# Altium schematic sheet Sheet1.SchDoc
size A4
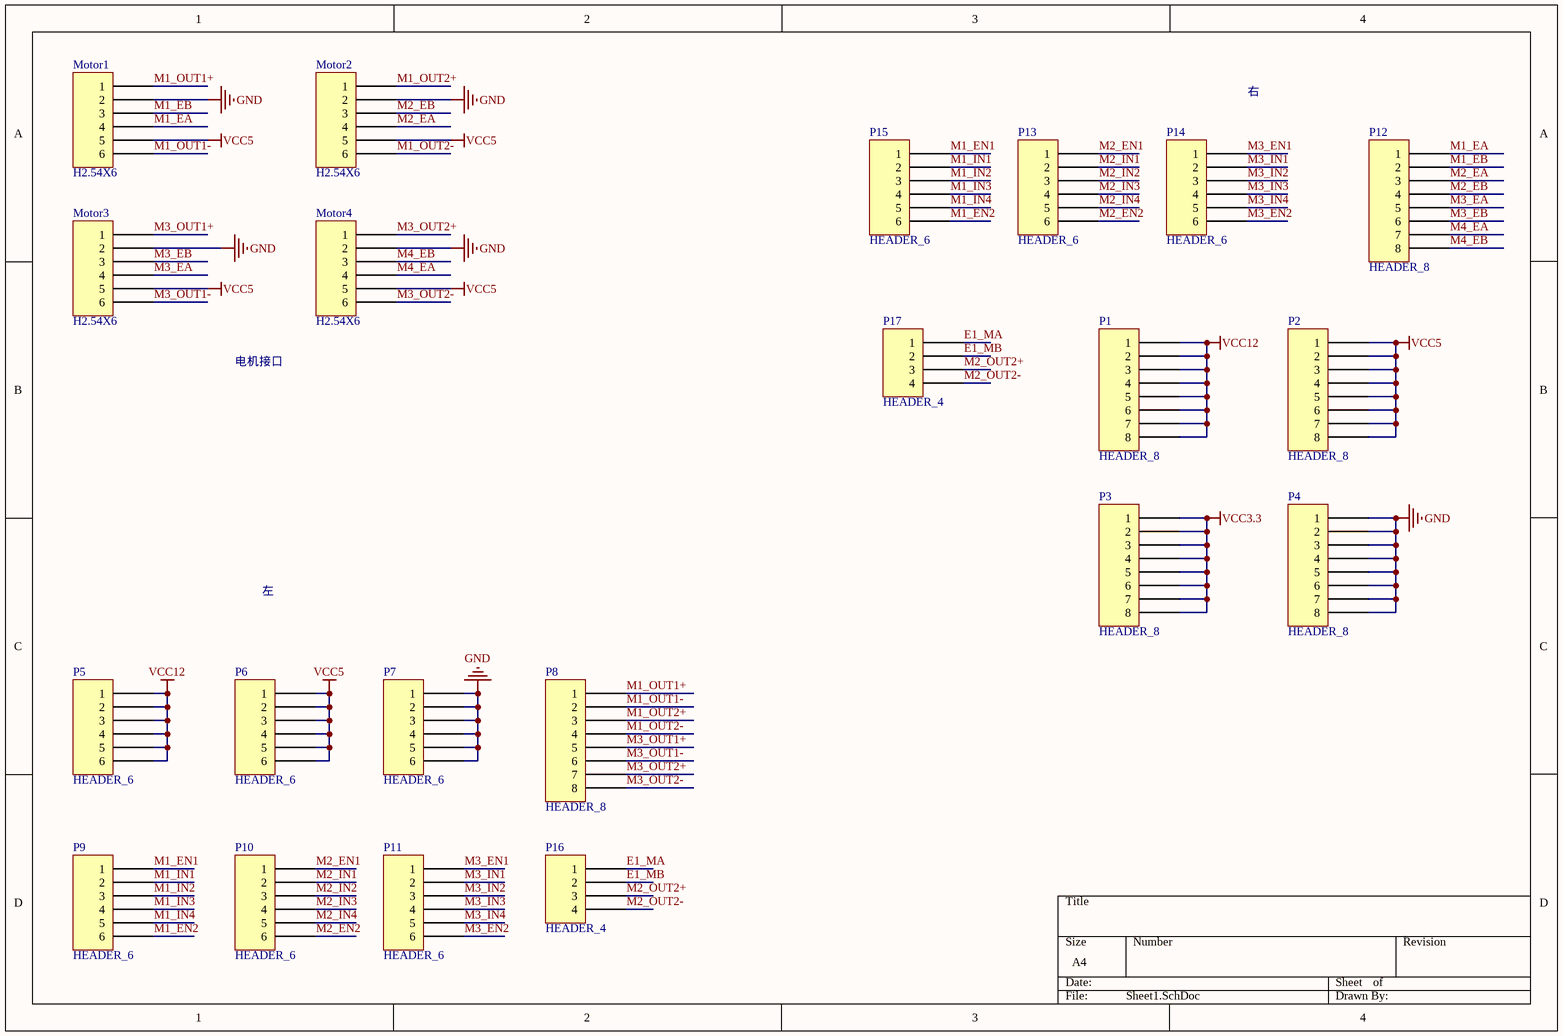
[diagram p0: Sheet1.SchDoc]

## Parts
Motor1  H2.54X6  [Header6]
Motor2  H2.54X6  [Header6]
Motor3  H2.54X6  [Header6]
Motor4  H2.54X6  [Header6]
P1  HEADER_8  [HDR1X8]
P2  HEADER_8  [HDR1X8]
P3  HEADER_8  [HDR1X8]
P4  HEADER_8  [HDR1X8]
P5  HEADER_6  [HDR1X6]
P6  HEADER_6  [HDR1X6]
P7  HEADER_6  [HDR1X6]
P8  HEADER_8  [HDR1X8]
P9  HEADER_6  [HDR1X6]
P10  HEADER_6  [HDR1X6]
P11  HEADER_6  [HDR1X6]
P12  HEADER_8  [HDR1X8]
P13  HEADER_6  [HDR1X6]
P14  HEADER_6  [HDR1X6]
P15  HEADER_6  [HDR1X6]
P16  HEADER_4  [HDR1X4]
P17  HEADER_4  [HDR1X4]

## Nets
GND: Motor1.2 Motor2.2 Motor3.2 Motor4.2 P4.1 P4.2 P4.3 P4.4 P4.5 P4.6 P4.7 P4.8 P7.1 P7.2 P7.3 P7.4 P7.5 P7.6
VCC3.3: P3.1 P3.2 P3.3 P3.4 P3.5 P3.6 P3.7 P3.8
VCC5: Motor1.5 Motor2.5 Motor3.5 Motor4.5 P2.1 P2.2 P2.3 P2.4 P2.5 P2.6 P2.7 P2.8 P6.1 P6.2 P6.3 P6.4 P6.5 P6.6
VCC12: P1.1 P1.2 P1.3 P1.4 P1.5 P1.6 P1.7 P1.8 P5.1 P5.2 P5.3 P5.4 P5.5 P5.6
E1_MA: P16.1 P17.1
E1_MB: P16.2 P17.2
M1_EA: Motor1.4 P12.1
M1_EB: Motor1.3 P12.2
M1_EN1: P9.1 P15.1
M1_EN2: P9.6 P15.6
M1_IN1: P9.2 P15.2
M1_IN2: P9.3 P15.3
M1_IN3: P9.4 P15.4
M1_IN4: P9.5 P15.5
M1_OUT1+: Motor1.1 P8.1
M1_OUT1-: Motor1.6 P8.2
M1_OUT2+: Motor2.1 P8.3
M1_OUT2-: Motor2.6 P8.4
M2_EA: Motor2.4 P12.3
M2_EB: Motor2.3 P12.4
M2_EN1: P10.1 P13.1
M2_EN2: P10.6 P13.6
M2_IN1: P10.2 P13.2
M2_IN2: P10.3 P13.3
M2_IN3: P10.4 P13.4
M2_IN4: P10.5 P13.5
M2_OUT2+: P16.3 P17.3
M2_OUT2-: P16.4 P17.4
M3_EA: Motor3.4 P12.5
M3_EB: Motor3.3 P12.6
M3_EN1: P11.1 P14.1
M3_EN2: P11.6 P14.6
M3_IN1: P11.2 P14.2
M3_IN2: P11.3 P14.3
M3_IN3: P11.4 P14.4
M3_IN4: P11.5 P14.5
M3_OUT1+: Motor3.1 P8.5
M3_OUT1-: Motor3.6 P8.6
M3_OUT2+: Motor4.1 P8.7
M3_OUT2-: Motor4.6 P8.8
M4_EA: Motor4.4 P12.7
M4_EB: Motor4.3 P12.8

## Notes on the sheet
- 右
- 电机接口
- 左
